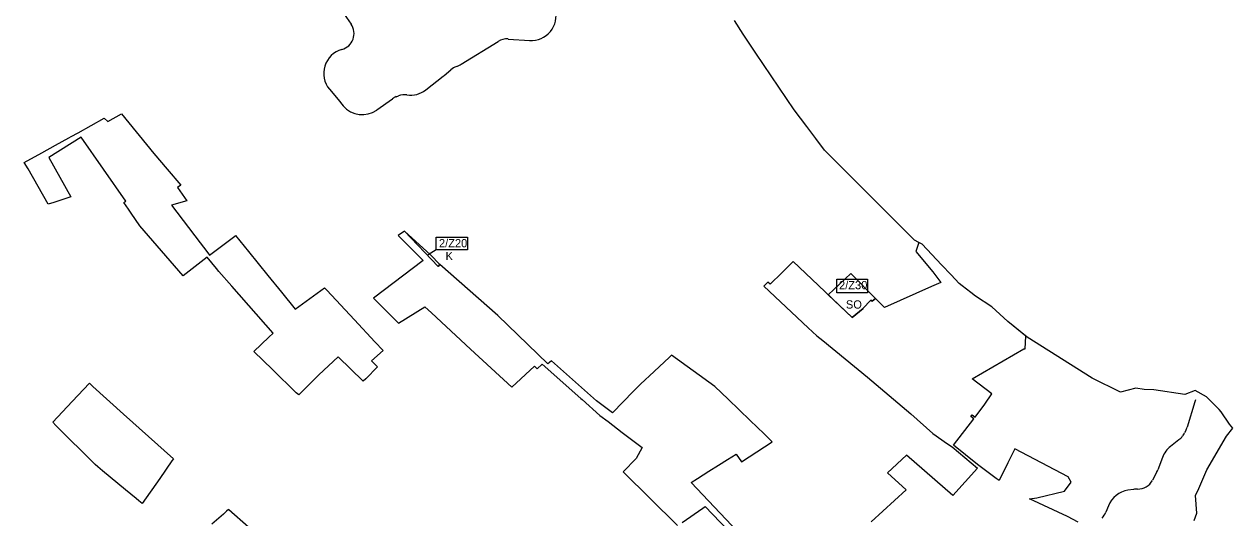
# Model space of a CAD drawing. Extents: x -445049 to -440454, y -1148980 to -1129741.
# Drawn here: x -441915 to -440454, y -1131508 to -1130912 of the extents above; entities that cross this region are included whole.
import ezdxf

# ---------------------------------------------------------------- set-up
doc = ezdxf.new("R2010")
doc.units = 0
for name, color, linetype in [('Vrstva 23', 7, 'Continuous'), ('Vrstva 3', 7, 'Continuous'), ('Vrstva 4', 7, 'Continuous'), ('Vrstva 5', 7, 'Continuous'), ('Vrstva 7', 7, 'Continuous'), ('Vrstva 8', 7, 'Continuous')]:
    doc.layers.add(name, color=color, linetype=linetype)

msp = doc.modelspace()

# ---------------------------------------------------------------- linework, layer by layer
at = {"layer": 'Vrstva 23'}
for p, q in [((-441533.4, -1130891.4), (-441519.4, -1130911.6)), ((-441329.8, -1130929.5), (-441303.6, -1130931.2)), ((-441386.3, -1130960), (-441341.6, -1130932.4)), ((-441406.9, -1130973.6), (-441399, -1130966.7)), ((-441429.3, -1130991.1), (-441408.2, -1130974.6)), ((-441545.6, -1130990.3), (-441535.2, -1131002.8)), ((-441535.2, -1131002.8), (-441529, -1131010.2)), ((-441488.4, -1131015.3), (-441469.5, -1131001.7)), ((-441464.9, -1130999.2), (-441462, -1130998.1)), ((-440499.5, -1131368), (-440509, -1131398.9)), ((-440513, -1131406.9), (-440514.6, -1131409.3)), ((-440510.6, -1131402.7), (-440512.2, -1131405.6)), ((-440519, -1131414), (-440529.1, -1131421.9)), ((-440538.8, -1131435.2), (-440544.4, -1131450.4)), ((-440545.5, -1131452.9), (-440550.9, -1131463)), ((-440573.8, -1131473.9), (-440580.6, -1131474.9)), ((-440604.1, -1131493.8), (-440607.1, -1131501.4))]:
    msp.add_line(p, q, dxfattribs=at)
for centre, radius, start, end in [((-441301.7, -1130901.3), 30, 266.2055, 14.2307), ((-441535.9, -1130922.9), 20, 285.4715, 34.6415), ((-441331.1, -1130949.4), 20, 86.2055, 121.7119), ((-441522.6, -1130971.1), 30, 105.4715, 219.7756), ((-441426.6, -1130950.9), 30, 307.8168, 310.9778), ((-441385.8, -1130981.8), 20, 108.933, 130.9778), ((-441402.1, -1130934.5), 30, 288.933, 301.7119), ((-441512.2, -1130983.6), 30, 219.7756, 219.7804), ((-441457.8, -1131017.9), 20, 110.6573, 125.8046), ((-441455, -1131016.8), 20, 81.6928, 110.6573), ((-441447.7, -1130967.4), 30, 261.6928, 307.8168), ((-441506, -1130991), 30, 219.7804, 305.8046), ((-440470.8, -1131376.8), 30, 158.4626, 162.8665), ((-440531.3, -1131398.3), 20, 307.9803, 326.5923), ((-440529.7, -1131395.9), 20, 326.5923, 330.8682), ((-440528.1, -1131393), 20, 330.8682, 342.8665), ((-440510.6, -1131445.6), 30, 127.9803, 159.7554), ((-440563.1, -1131443.5), 20, 331.9075, 339.7554), ((-440568.5, -1131453.6), 20, 269.074, 331.9075), ((-440576.1, -1131504.6), 30, 98.4856, 158.814), ((-440569.3, -1131503.6), 30, 89.074, 98.4856), ((-440625.7, -1131494.2), 20, 313.8057, 338.814)]:
    msp.add_arc(centre, radius, start, end, dxfattribs=at)
at = {"layer": 'Vrstva 3'}
msp.add_line((-441416.5, -1131184.4), (-441426.4, -1131190.3), dxfattribs=at)
msp.add_line((-441416.5, -1131184.4), (-441426.4, -1131190.3), dxfattribs=at)
for points in [[(-441416.5, -1131169.1), (-441378.9, -1131169.1), (-441378.9, -1131184.4), (-441416.5, -1131184.4)], [(-440932.4, -1131219.7), (-440895.4, -1131219.7), (-440895.4, -1131236.4), (-440932.4, -1131236.4)]]:
    msp.add_lwpolyline(points, close=True, dxfattribs=at)
at = {"layer": 'Vrstva 5'}
msp.add_lwpolyline([(-440500.5, -1131511.6), (-440497.2, -1131502.5), (-440498.7, -1131481.2), (-440494.9, -1131472.7), (-440485, -1131450.2), (-440461.2, -1131409.7), (-440453.7, -1131400.1), (-440457.9, -1131395.3), (-440467.7, -1131380), (-440470.4, -1131377.2), (-440472.6, -1131375), (-440485.6, -1131362.1), (-440499.2, -1131354.5), (-440511.6, -1131359.4), (-440549.4, -1131353.5), (-440561.1, -1131353.1), (-440570.9, -1131351.7), (-440589.4, -1131356.6), (-440623.6, -1131339.4), (-440702.5, -1131289.8), (-440725.5, -1131270.9), (-440745, -1131253.1), (-440764.9, -1131240.4), (-440770.5, -1131235.9), (-440780.7, -1131227.9), (-440784.5, -1131224.9), (-440794.1, -1131214.7), (-440805.7, -1131202.3), (-440829.2, -1131177.4), (-440833.3, -1131175.3), (-440838.5, -1131172.5), (-440880.7, -1131130.4), (-440905.4, -1131105.9), (-440919.4, -1131091.6), (-440929.8, -1131081.2), (-440947.1, -1131063.8), (-440957.6, -1131049.8), (-440968.5, -1131035.3), (-440983.8, -1131015.1), (-441030.2, -1130946.6), (-441045.4, -1130923.5), (-441056, -1130907.3)], dxfattribs=at)
at = {"layer": 'Vrstva 7'}
for points in [[(-441858.1, -1131120.3), (-441878.7, -1131127), (-441885.5, -1131129.2), (-441909.8, -1131086.3), (-441914.6, -1131078.7), (-441893.4, -1131067.1), (-441876.8, -1131058), (-441860.5, -1131048.9), (-441857.8, -1131047.5), (-441849.5, -1131042.9), (-441818.1, -1131025.2), (-441813.5, -1131029.4), (-441797.2, -1131019.9), (-441757.8, -1131067.9), (-441741.8, -1131086.7), (-441725.3, -1131106.1), (-441729.5, -1131108.9), (-441718.2, -1131125.1), (-441736.7, -1131130.5), (-441702, -1131175.8), (-441693.9, -1131186.4), (-441690.5, -1131190.9), (-441660.2, -1131167.9), (-441659.2, -1131167.1), (-441643.6, -1131186.2), (-441620, -1131215.3), (-441603.5, -1131235.6), (-441586.9, -1131255.9), (-441551.6, -1131230.2), (-441548.7, -1131233.3), (-441515.3, -1131268.9), (-441490.7, -1131295.5), (-441480.7, -1131306.2), (-441495, -1131318.5), (-441487.5, -1131325.6), (-441501.5, -1131340.1), (-441505, -1131343.2), (-441535, -1131313.8), (-441558.4, -1131335.3), (-441571.1, -1131348), (-441582.7, -1131359.7), (-441586, -1131357.1), (-441614.5, -1131328.9), (-441636.9, -1131307.1), (-441618.9, -1131290), (-441613.8, -1131285.2), (-441663.7, -1131228.3), (-441679.3, -1131210.6), (-441682.3, -1131206.9), (-441693.5, -1131193.3), (-441707.8, -1131204.3), (-441722.6, -1131215.8), (-441774.8, -1131155.2), (-441785.4, -1131139.9), (-441788.7, -1131135.1), (-441794.2, -1131127.1), (-441791.6, -1131125.5), (-441845.6, -1131048.2), (-441885, -1131072.6)], [(-441734.3, -1131437.1), (-441736, -1131439.5), (-441750.8, -1131460.6), (-441772.2, -1131490.9), (-441776.2, -1131487.6), (-441779.1, -1131485.1), (-441792, -1131474.5), (-441819.8, -1131451.5), (-441825.7, -1131446.7), (-441829, -1131443.7), (-441876.4, -1131396.6), (-441880.2, -1131392.7), (-441856.5, -1131367.6), (-441835.7, -1131345.6), (-441832.4, -1131348.9), (-441831.5, -1131349.7), (-441794.7, -1131383.2)]]:
    msp.add_lwpolyline(points, close=True, dxfattribs=at)
for points in [[(-441052.6, -1131524.9), (-441108.4, -1131465.5), (-441100.6, -1131460.6), (-441087.1, -1131452.1), (-441075.4, -1131444.7), (-441064.6, -1131438), (-441054, -1131431.3), (-441047.7, -1131440.7), (-441010.6, -1131416.5), (-441020.2, -1131406.7), (-441037.1, -1131390.5), (-441063.6, -1131364.9), (-441079.7, -1131349.4), (-441132.1, -1131311.6), (-441134.6, -1131314.1), (-441153.2, -1131331.3), (-441169.7, -1131346.6), (-441178.3, -1131355.4), (-441203.7, -1131381.5), (-441222.9, -1131366.9), (-441277.3, -1131318.4), (-441279.7, -1131320.6), (-441281.5, -1131322.3), (-441342.2, -1131263.7), (-441412.2, -1131202.1), (-441414.3, -1131204.7), (-441454.9, -1131161.6), (-441462.4, -1131167), (-441459.8, -1131169.7), (-441432.5, -1131197.3), (-441492.3, -1131242.6), (-441462.1, -1131273.1), (-441430.3, -1131253.1), (-441422.2, -1131260.7), (-441375, -1131304.3), (-441325.1, -1131350.5), (-441298, -1131325.1), (-441294.7, -1131328.2), (-441288.6, -1131322.7), (-441241.7, -1131364.2), (-441240.3, -1131365.3), (-441218.9, -1131384.7), (-441208.6, -1131391.9), (-441191.7, -1131405.3), (-441171, -1131420.7), (-441167.8, -1131423.5), (-441175, -1131436.8), (-441190.7, -1131452.7), (-441124.8, -1131517.8)], [(-440640.8, -1131513.4), (-440653.7, -1131506.7), (-440699.5, -1131485.3), (-440690.6, -1131484.2), (-440657.2, -1131476.2), (-440649.1, -1131465.4), (-440652.6, -1131458.7), (-440717.4, -1131424.8), (-440725.7, -1131441.7), (-440736.1, -1131463.4), (-440739.9, -1131460.8), (-440762.5, -1131443.7), (-440791.5, -1131420.4), (-440766.8, -1131388.6), (-440770.3, -1131385.8), (-440768.9, -1131383.7), (-440765.1, -1131386.7), (-440753.5, -1131370.9), (-440745.1, -1131358.6), (-440768.9, -1131340.4), (-440706.3, -1131304.1), (-440704.6, -1131303.9), (-440703.9, -1131288.7), (-440725.5, -1131270.9), (-440745, -1131253.1), (-440764.9, -1131240.4), (-440770.5, -1131235.9), (-440780.7, -1131227.9), (-440784.5, -1131224.9), (-440794.1, -1131214.7), (-440805.7, -1131202.3), (-440829.2, -1131177.4), (-440833.3, -1131175.3), (-440836.9, -1131186.4), (-440816.5, -1131211.1), (-440806.8, -1131223.7), (-440817.8, -1131228.6), (-440874.7, -1131254.1), (-440882.7, -1131245.9), (-440885.6, -1131243), (-440889.7, -1131246.4), (-440891.1, -1131245.1), (-440900.8, -1131255.1), (-440900.6, -1131255.3), (-440913.8, -1131266.1)], [(-440913.8, -1131266.1), (-440962.6, -1131219.7), (-440985.1, -1131198.4), (-440999, -1131212.1), (-441012.9, -1131225.9), (-441015.8, -1131223.3), (-441020.7, -1131228.2), (-440966.9, -1131278.5), (-440956.4, -1131288.3), (-440949.4, -1131294)], [(-440949.4, -1131294), (-440895.4, -1131338.2), (-440843.1, -1131382.5), (-440816.2, -1131406.3), (-440798.5, -1131418.7), (-440793.1, -1131422.4), (-440762.2, -1131448.1), (-440792.2, -1131481.2), (-440848.2, -1131432.5), (-440871.1, -1131453.9), (-440848.4, -1131474.5), (-440891, -1131513.3)], [(-441643.5, -1131519.6), (-441667.4, -1131498.7), (-441667.7, -1131498.4), (-441670, -1131500.4), (-441673.7, -1131503.7), (-441687.8, -1131515.9)], [(-441119.3, -1131514), (-441094.4, -1131496.6), (-441091.5, -1131494.5), (-441054.9, -1131532.9)]]:
    msp.add_lwpolyline(points, dxfattribs=at)
at = {"layer": 'Vrstva 8'}
msp.add_lwpolyline([(-441454.9, -1131161.6), (-441414.3, -1131204.7), (-441412.2, -1131202.1), (-441423.5, -1131190.4)], close=True, dxfattribs=at)
msp.add_lwpolyline([(-440942.7, -1131238.6), (-440913.8, -1131266.1), (-440900.6, -1131255.3), (-440900.8, -1131255.1), (-440891.1, -1131245.1), (-440889.7, -1131246.4), (-440885.6, -1131243), (-440915.4, -1131212.8), (-440942.7, -1131238.6)], dxfattribs=at)

# ---------------------------------------------------------------- texts
at = {"layer": 'Vrstva 3'}
for s, p in [('2/Z20', (-441413.3, -1131181.3)), ('2/Z30', (-440929.7, -1131232))]:
    msp.add_text(s, height=10, dxfattribs=at).set_placement(p)
at = {"layer": 'Vrstva 4'}
for s, p in [('K', (-441405.3, -1131196.8)), ('SO', (-440921.4, -1131255.4))]:
    msp.add_text(s, height=10, dxfattribs=at).set_placement(p)

doc.saveas('drawing.dxf')
